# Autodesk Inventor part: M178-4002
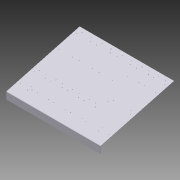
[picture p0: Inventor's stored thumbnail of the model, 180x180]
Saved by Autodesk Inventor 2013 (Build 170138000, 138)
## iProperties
Created: 2004-11
Part Number: M178-4002
Material: Aluminium - 6061
Document SubType Name: Sheet Metal
Designer: Autodesk, Inc.
Manufacturer: Standard
Standards Organization: Custom
Description: TOOL CADDY, MAIN PLATE
Mass: 1050.71 g
Surface Area: 5130.27 cm^2
Volume: 387.717 cm^3
Density: 2.71 g/cm^3
Flat Pattern Width: 47.2535 cm
Flat Pattern Length: 53.975 cm
Flat Pattern Area: 2550.51 cm^2
Sheet Metal Rule: Default
Sheet Metal Width: 18.604 in
Sheet Metal Length: 21.250 in
Sheet Metal Area: 395.330 in^2
CAGE: 1LJX3
Dept. ID: Product Design
Description #2: ---
Finish #1: ---
Finish #2: ---
Material ID: ---
Project Number: ---
Author: Autodesk, Inc.
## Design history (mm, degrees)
node "Face1"
node "Flange1"
sketch "Sketch3"
  geometry: L1 (0, 0)-(0, 37.661) reference; 2 further points
  constraints: 1 horizontal alignment, 1 midpoint
  dimensions: "d10" = 25.4 distance from line of point (25.4, 18.831) L1
hole "Hole1" sketch "Sketch3" diameter "d11" = 8; stored, may be unused: countersink angle "d15" = 82 deg, drill point angle "d17" = 118 deg; dims "d12" = 12.7, "d13" = 9.525, "d14" = 6.35, "d16" = 1.524 (= Thickness)
pattern_linear "Rectangular Pattern1" dims "d20" = 488.95 (= d1 - 2 x d10)
cut "Cut1" dims "d21" = 1.524 (= Thickness), "d22" = 0
cut "Cut2" dims "d23" = 1.524 (= Thickness), "d24" = 0
cut "Cut3" dims "d25" = 1.524 (= Thickness), "d26" = 0
cut "Cut4" dims "d27" = 1.524 (= Thickness), "d28" = 0
pattern_linear "Rectangular Pattern2" dims "d31" = 95.25
pattern_linear "Rectangular Pattern3" dims "d34" = 95.25
pattern_linear "Rectangular Pattern4" dims "d37" = 114.3
cut "Cut5" dims "d38" = 1.524 (= Thickness), "d39" = 0
pattern_linear "Rectangular Pattern5" dims "d42" = 406.4
body "Solid1"
sketch "Sketch4"
  geometry: C1 r 1.588 at (521.652, -368.501) reference; C2 r 1.588 at (521.652, -238.326) reference; C3 r 1.588 at (508, -221.499) reference; C4 r 1.588 at (406.4, -221.499) reference; C5 r 1.588 at (392.747, -238.326) reference; C6 r 1.588 at (392.747, -368.501) reference; C7 r 1.588 at (369.252, -368.501) reference; C8 r 1.588 at (369.252, -289.126) reference; C9 r 1.588 at (355.6, -272.299) reference; C10 r 1.588 at (317.5, -272.299) reference; C11 r 1.588 at (303.847, -289.126) reference; C12 r 1.588 at (303.847, -368.501) reference; C13 r 1.588 at (521.653, -89.101) reference; C14 r 1.588 at (521.653, -35.126) reference; C15 r 1.588 at (508, -18.299) reference; C16 r 1.588 at (469.9, -18.299) reference; C17 r 1.588 at (456.247, -35.126) reference; C18 r 1.588 at (456.247, -89.101) reference; C19 r 1.588 at (324.802, -35.126) reference; C20 r 1.588 at (324.802, -139.901) reference; C21 r 1.588 at (311.15, -18.299) reference; C22 r 1.588 at (260.35, -18.299) reference; C23 r 1.588 at (246.697, -35.126) reference; C24 r 1.588 at (246.697, -139.901) reference
  constraints: 24 centre point, 48 other
sketch "Sketch1"
  geometry: L1 (-269.875, 20)-(269.875, 20); L2 (269.875, 20)-(269.875, -20); L3 (269.875, -20)-(-269.875, -20); L4 (-269.875, -20)-(-269.875, 20); 3 further points
  constraints: 8 end point, 2 midpoint, 2 parallel, 1 horizontal, 1 horizontal alignment, 1 perpendicular, 1 vertical alignment
  dimensions: "d0" = 40 distance of L1.end L2.end; "d1" = 539.75 distance of L1.start L1.end
face "Plate1" dims "Thickness" = 1.524
sketch "Sketch2"
  geometry: L1 through (269.875, 0) direction (1, 0); L2 (539.75, 0)-(539.75, -434.34); L3 (539.75, -434.34)-(0, -434.34); L4 through (0, -217.17) direction (-0, 1)
  constraints: 6 end point, 1 horizontal, 1 perpendicular, 1 vertical
face "Plate2" dims "d3" = 1.524 (= BendReliefWidth), "d5" = 3.048 (= MinimumRemnant), "d7" = 434.34, "d8" = 105 deg, "d9" = 1.524 (= BendRadius), "Thickness" = 1.524
bend "Bend1" dims "d3" = 1.524 (= BendReliefWidth), "d4" = 0.762 (= BendReliefDepth), "d5" = 3.048 (= MinimumRemnant), "d6" = 1.524 (= BendRadius), "d7" = 434.34, "d8" = 105 deg, "d9" = 1.524 (= BendRadius), "SeamGap" = 0.00508, "Thickness" = 1.524
sketch "Sketch5"
  geometry: C1 r 1.588 at (67.437, 353.66) reference; C2 r 1.588 at (67.437, 379.06) reference
  constraints: 2 centre point, 4 other
node "FlatPattern"
feature "Definition2" dims "d0" = 1.524 (derived)
other parameters: "BendRadius" = 1.524 (= Thickness), "BendReliefWidth" = 1.524 (= Thickness), "BendReliefDepth" = 0.762 (= 0.5 x Thickness), "CornerReliefSize" = 6.096 (= 4 x Thickness), "MinimumRemnant" = 3.048 (= 2 x Thickness), "TransitionRadius" = 1.524 (= BendRadius), "d2" = 1.524 (= BendRadius), "JacobiRadiusSize" = 1.524 (= Thickness), "GapSize" = 1.524 (= Thickness), "BendRadius" = 1.524, "BendReliefDepth" = 0.762, "BendReliefWidth" = 1.524, "CornerReliefSize" = 6.096, "JacobiRadiusSize" = 1.524, "MinimumRemnant" = 3.048, "Thickness" = 1.524, "TransitionRadius" = 1.524, "GapSize" = 1.524
